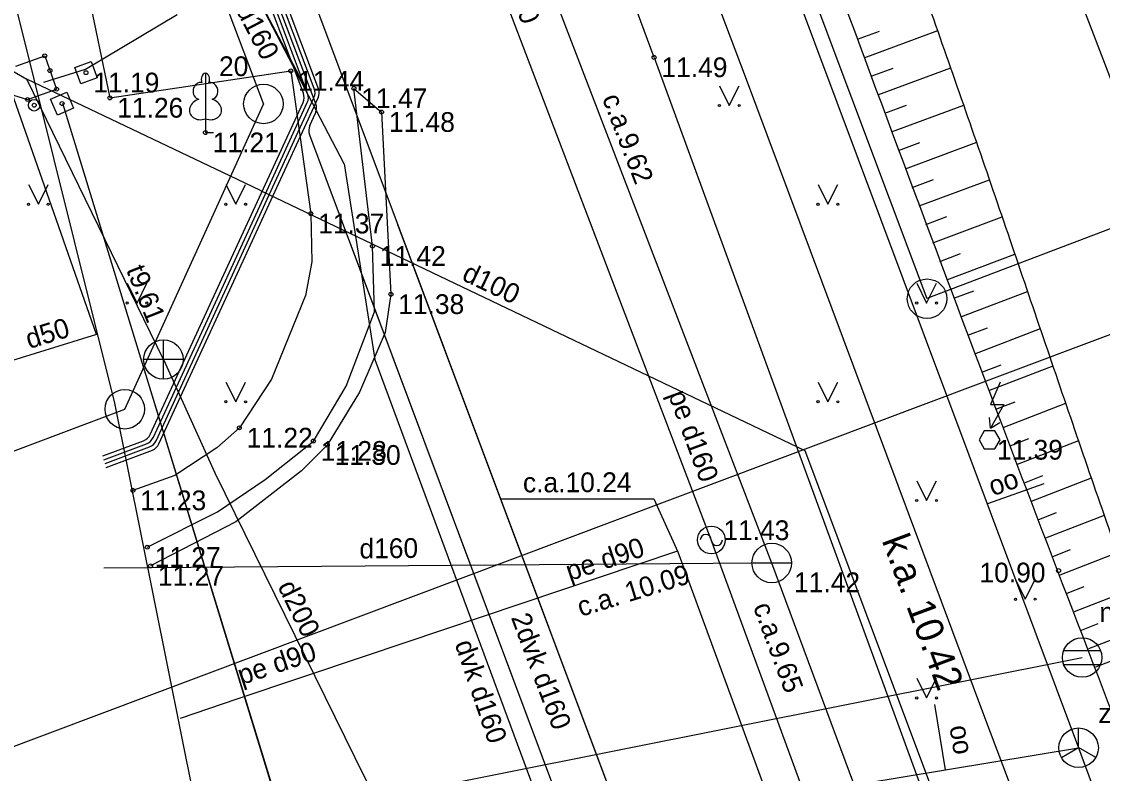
# Model space of a CAD drawing. Extents: x 503353 to 504004, y 304662 to 305049.
# Drawn here: x 503377.08 to 503404.45, y 304968.09 to 304987.12 of the extents above; entities that cross this region are included whole.
import ezdxf

# ---------------------------------------------------------------- set-up
doc = ezdxf.new("R2010")
doc.units = 0
for name, color, linetype in [('24', 7, 'Continuous'), ('25', 7, 'Continuous'), ('APGR_ELEM_####_####_#', 7, 'Continuous'), ('APGR_SARK_####_####_#', 7, 'Continuous'), ('APGS_VADP_ZSPR_####_#', 7, 'Continuous'), ('APGS_VADP_ZSPR_TKST_#', 7, 'Continuous'), ('BUVE_ELEM_####_####_#', 7, 'Continuous'), ('CELI_CMAL_####_####_#', 7, 'Continuous'), ('CKOM_ELEM_####_####_#', 7, 'Continuous'), ('DREN_VADP_####_####_#', 7, 'Continuous'), ('DREN_VADP_####_TKST_#', 7, 'Continuous'), ('ELEK_ACRL_####_####_#', 7, 'Continuous'), ('ELEK_ACRL_####_TKST_#', 7, 'Continuous'), ('ELEK_ELEM_####_####_#', 7, 'Continuous'), ('ELEK_VADP_VSPR_####_#', 7, 'Continuous'), ('ELEK_VADP_ZSPR_####_#', 7, 'Continuous'), ('GAZE_ELEM_####_####_#', 7, 'Continuous'), ('GAZE_ELEM_####_TKST_#', 7, 'Continuous'), ('GAZE_VADP_VSP1_####_#', 7, 'Continuous'), ('GAZE_VADP_VSP1_TKST_#', 7, 'Continuous'), ('GAZE_VADP_VSP2_####_#', 7, 'Continuous'), ('GAZE_VADP_VSP2_TKST_#', 7, 'Continuous'), ('HIDG_PLIN_####_####_#', 7, 'Continuous'), ('LKAN_ELEM_####_####_#', 7, 'Continuous'), ('LKAN_ELEM_PAST_TKST_#', 7, 'Continuous'), ('LKAN_VADP_PAST_####_#', 7, 'Continuous'), ('RAMI_UZMR_####_####_#', 7, 'Continuous'), ('RELJ_AATZ_####_TKST_#', 7, 'Continuous'), ('RELJ_ELEM_####_####_#', 7, 'Continuous'), ('RELJ_NOGA_####_####_#', 7, 'Continuous'), ('SAKK_ELEM_####_####_#', 7, 'Continuous'), ('SAKK_ELEM_####_TKST_#', 7, 'Continuous'), ('SAKK_IZVK_####_TKST_#', 7, 'Continuous'), ('SAKK_KKAN_####_####_#', 7, 'Continuous'), ('SKAN_DETP_SPDK_####_#', 7, 'Continuous'), ('SKAN_ELEM_####_####_#', 7, 'Continuous'), ('SKAN_VADP_PAST_####_#', 7, 'Continuous'), ('SKAN_VADP_PAST_TKST_#', 7, 'Continuous'), ('SKAN_VADP_SPDK_####_#', 7, 'Continuous'), ('SKAN_VADP_SPDK_TKST_#', 7, 'Continuous'), ('TERT_DIAM_####_TKST_#', 7, 'Continuous'), ('TERT_ELEM_####_####_#', 7, 'Continuous'), ('UDTK_ELEM_####_####_#', 7, 'Continuous'), ('UDTK_ELEM_####_TKST_#', 7, 'Continuous'), ('UDTK_VADP_UDEN_####_#', 7, 'Continuous'), ('UDTK_VADP_UDEN_TKST_#', 7, 'Continuous')]:
    doc.layers.add(name, color=color, linetype=linetype)

msp = doc.modelspace()

# ---------------------------------------------------------------- linework, layer by layer
at = {"layer": '24'}
msp.add_line((503375.886, 304968.402), (503401.316, 304977.953), dxfattribs=at)
at = {"layer": '25'}
for p, q in [((503405.924, 304982.367), (503395.906, 305008.647)), ((503401.316, 304977.953), (503406.819, 304980.02))]:
    msp.add_line(p, q, dxfattribs=at)
at = {"layer": 'APGR_ELEM_####_####_#'}
msp.add_line((503412.342, 304984.814), (503400.006, 304980.111), dxfattribs=at)
for centre in [(503383.2, 304985.04), (503400.01, 304980.11), (503379.69, 304977.31)]:
    msp.add_circle(centre, 0.5, dxfattribs=at)
at = {"layer": 'APGR_SARK_####_####_#'}
for p, q in [((503382.16, 305027.621), (503400.006, 304980.111)), ((503369.054, 305022.698), (503383.201, 304985.036)), ((503379.694, 304977.309), (503383.201, 304985.036)), ((503374.603, 304975.397), (503379.694, 304977.309))]:
    msp.add_line(p, q, dxfattribs=at)
at = {"layer": 'APGS_VADP_ZSPR_####_#'}
for p, q in [((503384.597, 304985.427), (503376.973, 305005.637)), ((503395.411, 304985.727), (503392.059, 304994.666)), ((503401.476, 304969.504), (503395.411, 304985.727)), ((503383.298, 304982.39), (503384.589, 304985.196)), ((503382.401, 304980.443), (503383.213, 304982.205)), ((503383.213, 304982.205), (503383.298, 304982.39)), ((503380.556, 304976.433), (503382.401, 304980.443)), ((503379.219, 304975.84), (503380.388, 304976.277)), ((503405.972, 304957.61), (503401.476, 304969.504))]:
    msp.add_line(p, q, dxfattribs=at)
for centre, start, end in [((503384.316, 304985.321), 335.2848, 20.6691), ((503380.283, 304976.558), 290.4959, 335.2848)]:
    msp.add_arc(centre, 0.3, start, end, dxfattribs=at)
at = {"layer": 'BUVE_ELEM_####_####_#'}
msp.add_circle((503377.395, 304985.009), 0.148, dxfattribs=at)
at = {"layer": 'CELI_CMAL_####_####_#'}
for points in [[(503393.097, 304986.219), (503379.573, 305022.746)], [(503383.156, 304989.838), (503382.652, 304989.382), (503378.744, 304987.921), (503379.313, 304985.194), (503383.895, 304985.877)], [(503393.097, 304986.219), (503403.273, 304958.405)], [(503383.895, 304985.877), (503384.402, 304982.262), (503384.427, 304981.04), (503384.264, 304980.193), (503383.408, 304978.075), (503382.592, 304976.84), (503382.017, 304976.331), (503380.955, 304975.631), (503379.894, 304975.254)], [(503380.26, 304973.819), (503382.036, 304974.716), (503383.248, 304975.533), (503384.467, 304976.505), (503385.301, 304977.893), (503386.015, 304979.78), (503385.963, 304981.441), (503385.494, 304985.434)], [(503385.494, 304985.434), (503386.193, 304984.833)], [(503386.193, 304984.833), (503386.429, 304980.222), (503386.284, 304979.257), (503385.639, 304977.74), (503384.819, 304976.403), (503384.166, 304975.754), (503382.502, 304974.464), (503380.342, 304973.344)]]:
    msp.add_lwpolyline(points, dxfattribs=at)
at = {"layer": 'CKOM_ELEM_####_####_#'}
msp.add_line((503401.617, 304976.835), (503401.858, 304976.974), dxfattribs=at)
msp.add_lwpolyline([(503401.866, 304977.997), (503401.617, 304977.434), (503401.953, 304977.434), (503401.617, 304976.835), (503401.595, 304977.105)], dxfattribs=at)
msp.add_lwpolyline([(503401.461, 304976.305), (503401.727, 304976.305), (503401.86, 304976.535), (503401.727, 304976.766), (503401.461, 304976.766), (503401.328, 304976.535)], close=True, dxfattribs=at)
at = {"layer": 'DREN_VADP_####_####_#'}
for q in [(503371.327, 305001.016), (503376.193, 304978.347)]:
    msp.add_line((503378.974, 304979.201), q, dxfattribs=at)
at = {"layer": 'ELEK_ACRL_####_####_#'}
for p, q in [((503384.269, 304985.458), (503381.835, 304990.062)), ((503386.601, 304981.987), (503392.927, 304965.13)), ((503385.387, 304981.535), (503391.699, 304964.676))]:
    msp.add_line(p, q, dxfattribs=at)
msp.add_lwpolyline([(503384.736, 304963.501), (503380.029, 304978.827)], dxfattribs=at)
at = {"layer": 'ELEK_ELEM_####_####_#'}
for points in [[(503378.993, 304985.703), (503378.574, 304985.548), (503378.421, 304985.961), (503378.84, 304986.116)], [(503378.393, 304984.935), (503377.982, 304984.76), (503377.809, 304985.165), (503378.22, 304985.34)]]:
    msp.add_lwpolyline(points, close=True, dxfattribs=at)
at = {"layer": 'ELEK_VADP_VSPR_####_#'}
for p, q in [((503384.489, 304985.431), (503375.688, 305008.76)), ((503385.249, 304983.527), (503381.733, 304990.255)), ((503383.249, 304982.523), (503384.481, 304985.199)), ((503385.249, 304983.527), (503386.023, 304978.574)), ((503382.416, 304980.714), (503383.249, 304982.523)), ((503380.482, 304976.512), (503382.416, 304980.714)), ((503386.023, 304978.574), (503391.594, 304963.529)), ((503379.191, 304975.936), (503380.314, 304976.356))]:
    msp.add_line(p, q, dxfattribs=at)
for centre, start, end in [((503384.208, 304985.325), 335.2848, 20.6691), ((503380.209, 304976.637), 290.4959, 335.2848)]:
    msp.add_arc(centre, 0.3, start, end, dxfattribs=at)
at = {"layer": 'ELEK_VADP_ZSPR_####_#'}
for p, q in [((503384.213, 304985.311), (503375.407, 305008.654)), ((503384.322, 304985.307), (503375.501, 305008.689)), ((503384.529, 304985.04), (503375.594, 305008.725)), ((503384.845, 304963.125), (503378.119, 304985.052)), ((503383.151, 304982.788), (503384.205, 304985.08)), ((503383.2, 304982.656), (503384.313, 304985.076)), ((503384.375, 304984.492), (503384.521, 304984.809)), ((503384.367, 304984.261), (503394.385, 304957.501)), ((503382.445, 304981.256), (503383.151, 304982.788)), ((503382.431, 304980.985), (503383.2, 304982.656)), ((503380.335, 304976.67), (503382.445, 304981.256)), ((503380.408, 304976.591), (503382.431, 304980.985)), ((503379.134, 304976.129), (503380.167, 304976.515)), ((503379.162, 304976.033), (503380.241, 304976.436))]:
    msp.add_line(p, q, dxfattribs=at)
for points in [[(503379.852, 305000), (503395.709, 304957.709)], [(503377.635, 304985.595), (503378.697, 304985.923), (503381.014, 304987.308)]]:
    msp.add_lwpolyline(points, dxfattribs=at)
for centre, start, end in [((503383.933, 304985.205), 335.2848, 20.6691), ((503384.041, 304985.201), 335.2848, 20.6691), ((503384.248, 304984.934), 335.2848, 20.6691), ((503384.648, 304984.367), 155.2848, 200.5245), ((503380.062, 304976.796), 290.4959, 335.2848), ((503380.136, 304976.717), 290.4959, 335.2848)]:
    msp.add_arc(centre, 0.3, start, end, dxfattribs=at)
at = {"layer": 'GAZE_ELEM_####_####_#'}
msp.add_circle((503394.546, 304974.002), 0.35, dxfattribs=at)
for centre, start, end in [((503394.406, 304974.002), 0, 180), ((503394.686, 304974.002), 180, 0)]:
    msp.add_arc(centre, 0.14, start, end, dxfattribs=at)
at = {"layer": 'GAZE_VADP_VSP1_####_#'}
msp.add_line((503393.697, 304973.697), (503399.453, 304958.074), dxfattribs=at)
msp.add_lwpolyline([(503393.691, 304973.715), (503385.777, 304971.058)], dxfattribs=at)
at = {"layer": 'GAZE_VADP_VSP1_TKST_#'}
msp.add_lwpolyline([(503389.206, 304975.043), (503393.09, 304975.043), (503393.697, 304973.697)], dxfattribs=at)
at = {"layer": 'GAZE_VADP_VSP2_####_#'}
for p, q in [((503394.546, 304974.002), (503384.635, 305000)), ((503400.28, 304958.379), (503394.546, 304974.002))]:
    msp.add_line(p, q, dxfattribs=at)
for points in [[(503385.777, 304971.058), (503382.528, 304969.968)], [(503382.528, 304969.968), (503381.091, 304969.485)]]:
    msp.add_lwpolyline(points, dxfattribs=at)
at = {"layer": 'HIDG_PLIN_####_####_#'}
for points in [[(503419.587, 304952.537), (503416.755, 304959.536), (503412.876, 304969.575), (503409.221, 304979.701), (503405.654, 304989.86), (503402.036, 305000), (503392.74, 305025.488)], [(503411.469, 304955.877), (503406.678, 304968.605), (503404.887, 304973.537), (503403.172, 304978.498), (503401.476, 304983.466), (503399.743, 304988.42), (503397.13, 304995.726), (503394.508, 305003.029), (503389.116, 305017.581), (503386.254, 305025.055)]]:
    msp.add_spline(points, degree=3, dxfattribs=at)
at = {"layer": 'LKAN_ELEM_####_####_#'}
for p, q in [((503403.47, 304971.2), (503404.406, 304971.2)), ((503403.47, 304970.85), (503404.406, 304970.85))]:
    msp.add_line(p, q, dxfattribs=at)
msp.add_circle((503403.938, 304971.025), 0.5, dxfattribs=at)
at = {"layer": 'LKAN_VADP_PAST_####_#'}
msp.add_line((503381.928, 304966.643), (503403.938, 304971.025), dxfattribs=at)
at = {"layer": 'RAMI_UZMR_####_####_#'}
msp.add_lwpolyline([(503407.219, 305023.925), (503368.776, 305020.183), (503379.431, 304977.462), (503383.452, 304957.421), (503396.867, 304960.598), (503416.959, 304959.032), (503433.698, 304951.36), (503608.791, 304871.751), (503642.724, 304858.177), (503694.651, 304834.724), (503842.283, 304765.867)], dxfattribs=at)
at = {"layer": 'RELJ_ELEM_####_####_#'}
for centre in [(503377.661, 304986.259), (503393.097, 304986.219), (503377.794, 304985.885), (503378.707, 304985.832), (503383.895, 304985.877), (503385.494, 304985.434), (503377.962, 304985.415), (503379.313, 304985.194), (503377.227, 304985.153), (503377.395, 304985.009), (503378.101, 304985.05), (503386.193, 304984.833), (503381.733, 304984.316), (503384.402, 304982.262), (503385.963, 304981.441), (503386.429, 304980.222), (503382.592, 304976.84), (503384.467, 304976.505), (503384.819, 304976.403), (503379.894, 304975.254), (503380.26, 304973.819), (503380.342, 304973.344), (503403.341, 304973.225)]:
    msp.add_circle(centre, 0.05, dxfattribs=at)
at = {"layer": 'RELJ_NOGA_####_####_#'}
for p, q in [((503398.248, 304986.68), (503398.809, 304986.887)), ((503398.421, 304986.211), (503400.282, 304986.897)), ((503398.594, 304985.742), (503399.15, 304985.947)), ((503398.767, 304985.273), (503400.613, 304985.953)), ((503398.94, 304984.804), (503399.491, 304985.008)), ((503399.113, 304984.335), (503400.942, 304985.011)), ((503399.287, 304983.866), (503399.832, 304984.068)), ((503399.461, 304983.397), (503401.268, 304984.069)), ((503399.635, 304982.929), (503400.174, 304983.129)), ((503399.809, 304982.46), (503401.594, 304983.123)), ((503399.984, 304981.991), (503400.515, 304982.19)), ((503400.159, 304981.523), (503401.917, 304982.18)), ((503400.335, 304981.055), (503400.857, 304981.251)), ((503400.511, 304980.587), (503402.238, 304981.237)), ((503400.687, 304980.119), (503401.2, 304980.313)), ((503400.864, 304979.651), (503402.559, 304980.294)), ((503401.041, 304979.184), (503401.545, 304979.375)), ((503401.219, 304978.717), (503402.881, 304979.351)), ((503401.398, 304978.249), (503401.891, 304978.439)), ((503401.577, 304977.783), (503403.203, 304978.407)), ((503401.757, 304977.316), (503402.239, 304977.502)), ((503401.937, 304976.85), (503403.526, 304977.466)), ((503402.117, 304976.384), (503402.589, 304976.566)), ((503402.298, 304975.917), (503403.852, 304976.519)), ((503402.479, 304975.451), (503402.94, 304975.63)), ((503402.659, 304974.985), (503404.178, 304975.573)), ((503402.84, 304974.519), (503403.291, 304974.693)), ((503403.021, 304974.052), (503404.506, 304974.628)), ((503403.201, 304973.586), (503403.642, 304973.757)), ((503403.382, 304973.12), (503404.836, 304973.683)), ((503403.563, 304972.654), (503403.994, 304972.821)), ((503403.743, 304972.188), (503405.168, 304972.74)), ((503403.924, 304971.721), (503404.348, 304971.885)), ((503404.105, 304971.255), (503405.504, 304971.797)), ((503404.285, 304970.789), (503404.702, 304970.95))]:
    msp.add_line(p, q, dxfattribs=at)
for points in [[(503421.793, 304953.375), (503418.978, 304960.8), (503411.664, 304980.395), (503404.379, 305000), (503394.998, 305025.189)], [(503421.793, 304953.375), (503418.978, 304960.8), (503411.664, 304980.395), (503404.379, 305000), (503395.14, 305024.807)], [(503410.247, 304955.404), (503401.902, 304976.94), (503397.494, 304988.727), (503387.268, 305016.834), (503384.58, 305024.465)]]:
    msp.add_spline(points, degree=3, dxfattribs=at)
at = {"layer": 'SAKK_ELEM_####_####_#'}
for p, q in [((503403.851, 304968.743), (503403.851, 304969.242)), ((503403.417, 304968.493), (503403.851, 304968.743)), ((503403.851, 304968.743), (503403.85, 304968.742)), ((503404.284, 304968.493), (503403.851, 304968.743))]:
    msp.add_line(p, q, dxfattribs=at)
msp.add_circle((503403.85, 304968.741), 0.5, dxfattribs=at)
at = {"layer": 'SAKK_IZVK_####_TKST_#'}
for p, q in [((503402.973, 304975.423), (503401.538, 304974.914)), ((503400.196, 304969.832), (503400.468, 304968.183))]:
    msp.add_line(p, q, dxfattribs=at)
at = {"layer": 'SAKK_KKAN_####_####_#'}
for p, q in [((503402.973, 304975.423), (503401.538, 304974.915)), ((503400.196, 304969.833), (503400.468, 304968.183)), ((503382.355, 304965.193), (503403.85, 304968.741))]:
    msp.add_line(p, q, dxfattribs=at)
msp.add_lwpolyline([(503392.141, 305000), (503403.85, 304968.741), (503409.025, 304954.715)], dxfattribs=at)
at = {"layer": 'SKAN_DETP_SPDK_####_#'}
msp.add_line((503377.227, 304985.153), (503377.962, 304985.415), dxfattribs=at)
for points in [[(503376.926, 304985.997), (503377.661, 304986.259)], [(503377.661, 304986.259), (503377.962, 304985.415)], [(503376.765, 304985.58), (503376.873, 304985.259), (503377.227, 304985.153)]]:
    msp.add_lwpolyline(points, dxfattribs=at)
at = {"layer": 'SKAN_ELEM_####_####_#'}
for p, q in [((503380.667, 304978.069), (503380.667, 304979.069)), ((503381.167, 304978.569), (503380.167, 304978.569))]:
    msp.add_line(p, q, dxfattribs=at)
msp.add_circle((503380.667, 304978.569), 0.5, dxfattribs=at)
at = {"layer": 'SKAN_VADP_PAST_####_#'}
for p, q in [((503375.647, 304986.561), (503377.209, 304985.67)), ((503380.667, 304978.569), (503377.209, 304985.67)), ((503380.667, 304978.569), (503381.968, 304975.699)), ((503381.968, 304975.699), (503385.519, 304968.497)), ((503385.519, 304968.497), (503391.188, 304956.999))]:
    msp.add_line(p, q, dxfattribs=at)
at = {"layer": 'SKAN_VADP_SPDK_####_#'}
for p, q in [((503382.546, 304983.125), (503377.209, 304985.67)), ((503383.129, 304982.847), (503382.546, 304983.125)), ((503383.129, 304982.847), (503396.919, 304976.27)), ((503396.919, 304976.27), (503403.923, 304957.613))]:
    msp.add_line(p, q, dxfattribs=at)
at = {"layer": 'TERT_ELEM_####_####_#'}
for p, q in [((503394.75, 304985.5), (503395, 304985)), ((503395, 304985), (503395.25, 304985.5)), ((503381.733, 304984.663), (503381.733, 304984.316)), ((503381.733, 304984.316), (503381.933, 304984.316)), ((503377.25, 304983), (503377.5, 304982.5)), ((503377.5, 304982.5), (503377.75, 304983)), ((503382.25, 304983), (503382.5, 304982.5)), ((503382.5, 304982.5), (503382.75, 304983)), ((503397.25, 304983), (503397.5, 304982.5)), ((503397.5, 304982.5), (503397.75, 304983)), ((503379.75, 304980.5), (503380, 304980)), ((503380, 304980), (503380.25, 304980.5)), ((503399.75, 304980.5), (503400, 304980)), ((503400, 304980), (503400.25, 304980.5)), ((503382.25, 304978), (503382.5, 304977.5)), ((503382.5, 304977.5), (503382.75, 304978)), ((503397.25, 304978), (503397.5, 304977.5)), ((503397.5, 304977.5), (503397.75, 304978)), ((503399.75, 304975.5), (503400, 304975)), ((503400, 304975), (503400.25, 304975.5)), ((503402.25, 304973), (503402.5, 304972.5)), ((503402.5, 304972.5), (503402.75, 304973)), ((503399.75, 304970.5), (503400, 304970)), ((503400, 304970), (503400.25, 304970.5))]:
    msp.add_line(p, q, dxfattribs=at)
for points in [[(503381.733, 304985.816), (503381.733, 304984.663)], [(503381.823, 304985.584), (503381.822, 304985.585)]]:
    msp.add_lwpolyline(points, dxfattribs=at)
for centre, radius in [((503394.75, 304985), 0.028), ((503395.25, 304985), 0.0263), ((503377.25, 304982.5), 0.028), ((503377.75, 304982.5), 0.0263), ((503382.25, 304982.5), 0.028), ((503382.75, 304982.5), 0.0263), ((503397.25, 304982.5), 0.028), ((503397.75, 304982.5), 0.0263), ((503379.75, 304980), 0.028), ((503380.25, 304980), 0.0263), ((503399.75, 304980), 0.028), ((503400.25, 304980), 0.0263), ((503382.25, 304977.5), 0.028), ((503382.75, 304977.5), 0.0263), ((503397.25, 304977.5), 0.028), ((503397.75, 304977.5), 0.0263), ((503399.75, 304975), 0.028), ((503400.25, 304975), 0.0263), ((503402.25, 304972.5), 0.028), ((503402.75, 304972.5), 0.0263), ((503399.75, 304970), 0.028), ((503400.25, 304970), 0.0263)]:
    msp.add_circle(centre, radius, dxfattribs=at)
for centre, major_axis, ratio, start_param, end_param in [((503381.733, 304985.666), (0, -0.15), 0.707107, 3.14537, 5.287485), ((503381.733, 304985.666), (0, -0.15), 0.707107, 0.995701, 3.137816), ((503381.605, 304985.371), (-0.039, -0.212), 0.861323, 3.141593, 6.283185), ((503381.861, 304985.371), (0.039, -0.212), 0.861323, 0, 3.141593), ((503381.643, 304984.909), (0.307, 0.095), 0.814445, 1.570796, 4.752015), ((503381.823, 304984.909), (-0.307, 0.095), 0.814445, 1.531171, 4.712389)]:
    msp.add_ellipse(centre, major_axis=major_axis, ratio=ratio, start_param=start_param, end_param=end_param, dxfattribs=at)
at = {"layer": 'UDTK_ELEM_####_####_#'}
msp.add_line((503395.576, 304973.418), (503396.576, 304973.418), dxfattribs=at)
msp.add_circle((503396.076, 304973.418), 0.5, dxfattribs=at)
at = {"layer": 'UDTK_VADP_UDEN_####_#'}
msp.add_line((503396.075, 304973.418), (503401.683, 304958.302), dxfattribs=at)
for points in [[(503376.794, 305023.6), (503396.075, 304973.418)], [(503395.7, 304973.415), (503379.161, 304973.29)]]:
    msp.add_lwpolyline(points, dxfattribs=at)

# ---------------------------------------------------------------- texts
at = {"layer": 'APGS_VADP_ZSPR_TKST_#'}
msp.add_text('k.a. 10.42', height=0.7, rotation=290.4984, dxfattribs=at).set_placement((503398.858, 304973.989))
at = {"layer": 'DREN_VADP_####_TKST_#'}
msp.add_text('d50', height=0.5, rotation=17.0636, dxfattribs=at).set_placement((503377.268, 304978.834))
at = {"layer": 'ELEK_ACRL_####_TKST_#'}
for s, rotation, p in [('dvk d160', 297.5912, (503381.925, 304988.511)), ('2dvk d160', 290.5253, (503389.467, 304972.039)), ('dvk d160', 288.7157, (503388.042, 304971.376))]:
    msp.add_text(s, height=0.5, rotation=rotation, dxfattribs=at).set_placement(p)
at = {"layer": 'GAZE_ELEM_####_TKST_#'}
msp.add_text(' 11.43', height=0.5, dxfattribs=at).set_placement((503394.665, 304973.997))
at = {"layer": 'GAZE_VADP_VSP1_TKST_#'}
for s, rotation, p in [('c.a.10.24', 0.1571, (503389.776, 304975.207)), ('pe d90', 18.5565, (503390.958, 304972.956)), ('c.a. 10.09', 17.1513, (503391.241, 304972.052)), ('pe d90', 18.5565, (503382.646, 304970.324))]:
    msp.add_text(s, height=0.5, rotation=rotation, dxfattribs=at).set_placement(p)
at = {"layer": 'GAZE_VADP_VSP2_TKST_#'}
for s, rotation, p in [('d160', 290.8678, (503389.23, 304988.41)), ('pe d160', 290.1523, (503393.446, 304977.69))]:
    msp.add_text(s, height=0.5, rotation=rotation, dxfattribs=at).set_placement(p)
at = {"layer": 'LKAN_ELEM_PAST_TKST_#'}
msp.add_text('nozīme neskaidra', height=0.5, dxfattribs=at).set_placement((503404.376, 304971.922))
at = {"layer": 'RELJ_AATZ_####_TKST_#'}
for s, p in [(' 11.49', (503393.097, 304985.719)), (' 11.19', (503378.707, 304985.332)), (' 11.44', (503383.895, 304985.377)), (' 11.47', (503385.494, 304984.934)), (' 11.26', (503379.313, 304984.694)), (' 11.48', (503386.193, 304984.333)), (' 11.21', (503381.733, 304983.816)), (' 11.37', (503384.402, 304981.762)), (' 11.42', (503385.963, 304980.941)), (' 11.38', (503386.429, 304979.722)), (' 11.22', (503382.592, 304976.34)), (' 11.28', (503384.467, 304976.005)), (' 11.39', (503401.594, 304976.035)), (' 11.30', (503384.819, 304975.903)), (' 11.23', (503379.894, 304974.754)), (' 11.27', (503380.26, 304973.319)), (' 10.90', (503401.153, 304972.926)), (' 11.27', (503380.342, 304972.844))]:
    msp.add_text(s, height=0.5, dxfattribs=at).set_placement(p)
at = {"layer": 'SAKK_ELEM_####_TKST_#'}
msp.add_text('z.g.', height=0.5, dxfattribs=at).set_placement((503404.348, 304969.366))
at = {"layer": 'SAKK_IZVK_####_TKST_#'}
for rotation, p in [(19.5152, (503401.676, 304975.106)), (279.3732, (503400.576, 304969.273))]:
    msp.add_text('oo', height=0.5, rotation=rotation, dxfattribs=at).set_placement(p)
at = {"layer": 'SKAN_VADP_PAST_TKST_#'}
for s, rotation, p in [('t9.61', 291.7348, (503379.718, 304980.844)), ('d200', 296.2467, (503383.551, 304972.827))]:
    msp.add_text(s, height=0.5, rotation=rotation, dxfattribs=at).set_placement(p)
at = {"layer": 'SKAN_VADP_SPDK_TKST_#'}
msp.add_text('d100', height=0.5, rotation=334.5028, dxfattribs=at).set_placement((503388.199, 304980.595))
at = {"layer": 'TERT_DIAM_####_TKST_#'}
msp.add_text('20', height=0.5, dxfattribs=at).set_placement((503382.076, 304985.745))
at = {"layer": 'UDTK_ELEM_####_TKST_#'}
msp.add_text(' 11.42', height=0.5, dxfattribs=at).set_placement((503396.457, 304972.679))
at = {"layer": 'UDTK_VADP_UDEN_TKST_#'}
for s, rotation, p in [('c.a.9.62', 291.084, (503391.773, 304985.187)), ('d160', 0.5842, (503385.635, 304973.533)), ('c.a.9.65', 290.3561, (503395.598, 304972.314))]:
    msp.add_text(s, height=0.5, rotation=rotation, dxfattribs=at).set_placement(p)

doc.saveas('drawing.dxf')
